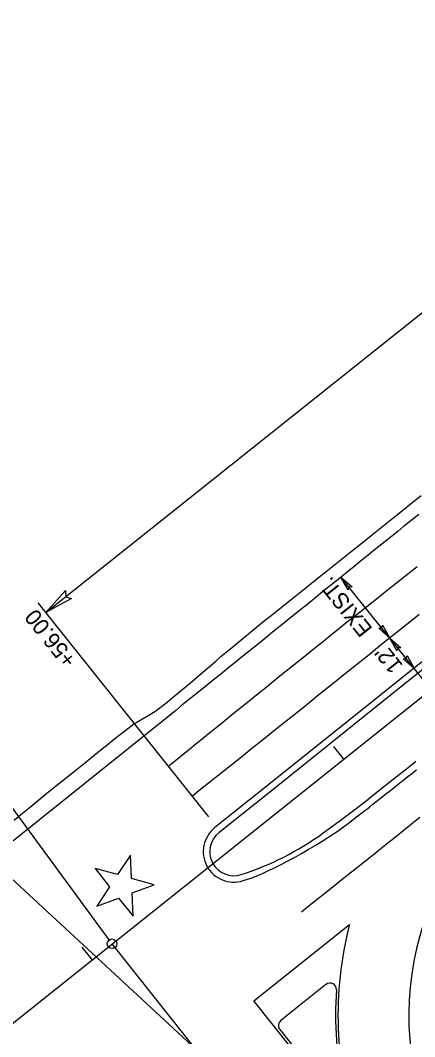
# Model space of a CAD drawing. Extents: x 472216 to 481979, y 489069 to 507339.
# Drawn here: x 473629 to 473751.6, y 506201.2 to 506517.1 of the extents above; entities that cross this region are included whole.
import ezdxf

# ---------------------------------------------------------------- set-up
doc = ezdxf.new("R2010")
doc.units = 0
for name, color, linetype in [('Old_Level_12', 7, 'Continuous'), ('Prop Drainage Structure Outlet Berm Ditch 850 10 CELL', 7, 'Continuous'), ('Prop Drainage Structure Pipe CSP 15in', 7, 'Continuous'), ('Prop Drainage Structure Pipe RCP 15in Class III Label', 7, 'Continuous'), ('Prop Drainage Structure Pipe RCP 18in Class III Label', 7, 'Continuous'), ('Prop Drainage Structure Pipe RCP 24in Class III Label', 7, 'Continuous'), ('Prop Erosion Embankment Toe Protection CELL', 7, 'Continuous'), ('Prop Erosion Embankment Toe Protection Label', 7, 'Continuous'), ('Prop Horizontal Alignment Station Label', 7, 'Continuous'), ('Sheet Block Revision CELL', 7, 'Continuous'), ('Sheet North Arrow Point CELL', 7, 'Continuous'), ('Sheet PE Seal Cell', 7, 'Continuous')]:
    doc.layers.add(name, color=color, linetype=linetype)

msp = doc.modelspace()

# ---------------------------------------------------------------- linework, layer by layer
at = {"layer": 'Old_Level_12'}
for p, q in [((473656.69, 506231.26), (473522.92, 506413.56)), ((473683.68, 506197.16), (473500.48, 506366.9))]:
    msp.add_line(p, q, dxfattribs=at)
msp.add_circle((473657.57, 506230.05), 1.5, dxfattribs=at)
msp.add_circle((473657.57, 506230.05), 1.5, dxfattribs=at)
msp.add_circle((473657.57, 506230.05), 1.5, dxfattribs=at)
msp.add_circle((473657.57, 506230.05), 1.5, dxfattribs=at)
at = {"layer": 'Prop Drainage Structure Outlet Berm Ditch 850 10 CELL'}
for points in [[(473730.91, 506340.03), (473728.7, 506344.03), (473732.15, 506341), (473731.17, 506340.94)], [(473644.98, 506337.41), (473636.98, 506333.01), (473643.05, 506339.9), (473643.15, 506337.94)], [(473741.65, 506329.09), (473743.86, 506325.09), (473740.41, 506328.12), (473741.39, 506328.17)], [(473746.07, 506321.09), (473743.86, 506325.09), (473747.31, 506322.06), (473746.33, 506322)], [(473749.23, 506319.62), (473751.44, 506315.62), (473747.98, 506318.65), (473748.97, 506318.71)]]:
    msp.add_lwpolyline(points, close=True, dxfattribs=at)
at = {"layer": 'Prop Drainage Structure Pipe RCP 15in Class III Label'}
for p, q in [((473701.63, 506212.36), (473731.35, 506236.06)), ((473733.69, 506171.98), (473701.63, 506212.36))]:
    msp.add_line(p, q, dxfattribs=at)
msp.add_arc((473839.76, 506207.93), 112, 165.4515, 198.722, dxfattribs=at)
at = {"layer": 'Prop Drainage Structure Pipe RCP 18in Class III Label'}
msp.add_lwpolyline([(473659.58, 506244.29), (473664.09, 506238.61), (473663.78, 506245.86), (473670.59, 506248.4), (473663.58, 506250.35), (473663.27, 506257.61), (473659.26, 506251.55), (473652.26, 506253.5), (473656.78, 506247.81), (473652.77, 506241.75), (473659.58, 506244.29)], dxfattribs=at)
msp.add_lwpolyline([(473659.58, 506244.29), (473664.09, 506238.61), (473663.78, 506245.86), (473670.59, 506248.4), (473663.58, 506250.35), (473663.27, 506257.61), (473659.26, 506251.55), (473652.26, 506253.5), (473656.78, 506247.81), (473652.77, 506241.75), (473659.58, 506244.29)], dxfattribs=at)
at = {"layer": 'Prop Drainage Structure Pipe RCP 24in Class III Label'}
for p, q in [((473600.83, 506241.3), (473676.26, 506301.73)), ((473698.32, 506249.68), (473701.36, 506250.67))]:
    msp.add_line(p, q, dxfattribs=at)
for points in [[(474009.26, 506521.83), (473992, 506508.53), (473990.3, 506507.18), (473981.12, 506499.85), (473971.51, 506492.2), (473962.33, 506484.88), (473952.75, 506477.25), (473943.6, 506469.95), (473934.44, 506462.65), (473924.91, 506455.03), (473915.79, 506447.72), (473906.27, 506440.08), (473897.18, 506432.8), (473888.11, 506425.54), (473877.44, 506416.99), (473868.47, 506409.76), (473855.37, 506399.15), (473839.04, 506386.02), (473812.65, 506364.8), (473778.08, 506337.11), (473740.52, 506306.99), (473705.74, 506279.1), (473689.48, 506266.16)], [(473752.86, 506363.48), (473750.91, 506361.92), (473748.95, 506360.36), (473748.26, 506359.81), (473746.32, 506358.24), (473744.37, 506356.67), (473742.43, 506355.1), (473740.48, 506353.53), (473738.54, 506351.96), (473736.6, 506350.4), (473734.65, 506348.83), (473732.71, 506347.26), (473730.76, 506345.69), (473728.82, 506344.12), (473726.87, 506342.55), (473724.93, 506340.99), (473722.98, 506339.42), (473721.04, 506337.85), (473719.09, 506336.28), (473717.15, 506334.71), (473715.2, 506333.14), (473713.26, 506331.58), (473711.31, 506330.01), (473709.37, 506328.44), (473707.42, 506326.87), (473705.48, 506325.3), (473703.54, 506323.73), (473701.59, 506322.17), (473699.65, 506320.6), (473697.7, 506319.03), (473695.76, 506317.46), (473693.81, 506315.89), (473691.87, 506314.32), (473689.92, 506312.76), (473687.98, 506311.19), (473686.03, 506309.62), (473684.09, 506308.05), (473682.14, 506306.48), (473680.2, 506304.91), (473679.17, 506304.08), (473677.23, 506302.51), (473675.29, 506300.94), (473674.72, 506300.49), (473674.64, 506300.43)], [(473701.31, 506250.65), (473703.61, 506251.62), (473704.11, 506251.83), (473706.37, 506252.89), (473707.86, 506253.59), (473710.08, 506254.72), (473712, 506255.69), (473714.2, 506256.88), (473716.4, 506258.08), (473718.55, 506259.35), (473720.7, 506260.61), (473722.81, 506261.96), (473724.63, 506263.12), (473726.72, 506264.48), (473726.96, 506264.63), (473727.8, 506265.21), (473729.06, 506266.1), (473731.07, 506267.58), (473731.6, 506267.96), (473733.57, 506269.5), (473735.54, 506271.03), (473737.51, 506272.57), (473738.63, 506273.44), (473740.6, 506274.99), (473742.56, 506276.54), (473744.04, 506277.71), (473746, 506279.26), (473747.96, 506280.81), (473749.91, 506282.37), (473750.16, 506282.57), (473752.12, 506284.12)]]:
    msp.add_lwpolyline(points, dxfattribs=at)
for centre, radius, start, end in [((473839.76, 506207.93), 90, 129.7563, 213.9898), ((473695.4, 506258.72), 9.5, 128.5099, 287.9281)]:
    msp.add_arc(centre, radius, start, end, dxfattribs=at)
at = {"layer": 'Prop Erosion Embankment Toe Protection CELL'}
for points in [[(474010.48, 506520.25), (473993.23, 506506.96), (473991.54, 506505.62), (473982.36, 506498.29), (473972.76, 506490.64), (473963.58, 506483.31), (473954, 506475.69), (473944.84, 506468.38), (473935.69, 506461.09), (473926.16, 506453.46), (473917.05, 506446.16), (473907.52, 506438.52), (473898.43, 506431.24), (473889.36, 506423.98), (473878.69, 506415.43), (473869.73, 506408.21), (473856.63, 506397.6), (473840.3, 506384.46), (473813.9, 506363.24), (473779.33, 506335.55), (473741.77, 506305.43), (473706.99, 506277.53), (473690.73, 506264.59)], [(473627.16, 506268.53), (473629.73, 506270.63), (473632.26, 506272.71), (473634.79, 506274.78), (473637.33, 506276.85), (473639.86, 506278.91), (473642.37, 506280.94), (473644.8, 506282.91), (473649.46, 506286.66), (473653.61, 506289.98), (473655.42, 506291.42), (473658.45, 506293.83), (473662.84, 506297.32), (473664.32, 506298.37), (473668.99, 506301.07), (473671.17, 506302.47), (473674.16, 506304.74), (473678, 506307.91), (473681.88, 506311.21), (473685.74, 506314.51), (473689.77, 506317.94), (473691.51, 506319.41), (473694.47, 506321.87), (473696.93, 506323.93), (473700.56, 506326.95), (473704.31, 506329.97), (473706.58, 506331.8), (473709.08, 506333.79), (473711.81, 506335.97), (473714.76, 506338.32), (473717.9, 506340.82), (473721.19, 506343.45), (473724.63, 506346.2), (473728.22, 506349.08), (473731.82, 506351.96), (473735.27, 506354.72), (473738.57, 506357.36), (473741.73, 506359.87), (473744.79, 506362.31), (473747.79, 506364.72), (473750.73, 506367.09), (473753.63, 506369.43)], [(473723.15, 506264.5), (473725.76, 506266.39), (473728.46, 506268.36), (473733.01, 506271.76), (473736.49, 506274.45), (473740.51, 506277.65), (473744.93, 506281.19), (473749.58, 506284.89), (473752.01, 506286.81)]]:
    msp.add_lwpolyline(points, dxfattribs=at)
for centre, radius, start, end in [((473695.4, 506258.72), 7.5, 128.5099, 287.772), ((473670.21, 506337.28), 90, 287.772, 306.0274)]:
    msp.add_arc(centre, radius, start, end, dxfattribs=at)
at = {"layer": 'Prop Erosion Embankment Toe Protection Label'}
for points in [[(473752.37, 506347.24), (473750.41, 506345.69), (473748.45, 506344.13), (473746.49, 506342.58), (473744.53, 506341.03), (473742.58, 506339.48), (473740.62, 506337.93), (473738.66, 506336.37), (473736.7, 506334.82), (473734.75, 506333.27), (473732.79, 506331.72), (473731.16, 506330.42), (473729.21, 506328.86), (473727.26, 506327.29), (473725.31, 506325.73), (473723.37, 506324.16), (473721.42, 506322.6), (473719.47, 506321.03), (473717.53, 506319.46), (473715.58, 506317.9), (473713.63, 506316.33), (473711.69, 506314.77), (473709.74, 506313.2), (473707.79, 506311.64), (473705.85, 506310.07), (473703.9, 506308.5), (473701.95, 506306.94), (473701.05, 506306.21), (473699.11, 506304.64), (473697.17, 506303.07), (473695.23, 506301.5), (473693.28, 506299.93), (473691.34, 506298.35), (473689.4, 506296.78), (473687.46, 506295.21), (473685.52, 506293.64), (473683.57, 506292.07), (473681.63, 506290.49), (473679.69, 506288.92), (473677.75, 506287.35), (473675.81, 506285.78), (473675.3, 506285.37)], [(473753.04, 506332.41), (473751.09, 506330.85), (473749.14, 506329.28), (473747.19, 506327.72), (473745.24, 506326.16), (473743.29, 506324.59), (473741.34, 506323.03), (473739.39, 506321.47), (473737.45, 506319.91), (473735.5, 506318.34), (473733.55, 506316.78), (473733.01, 506316.35), (473731.06, 506314.79), (473729.11, 506313.22), (473727.16, 506311.66), (473725.21, 506310.1), (473723.26, 506308.53), (473721.32, 506306.97), (473719.37, 506305.41), (473717.42, 506303.84), (473715.47, 506302.28), (473713.52, 506300.72), (473711.57, 506299.15), (473709.62, 506297.59), (473707.67, 506296.03), (473705.72, 506294.46), (473703.78, 506292.9), (473701.83, 506291.34), (473699.88, 506289.77), (473698.25, 506288.47), (473696.3, 506286.92), (473694.34, 506285.36), (473692.39, 506283.8), (473690.43, 506282.25), (473688.48, 506280.69), (473686.52, 506279.14), (473684.57, 506277.58), (473682.61, 506276.03), (473682.5, 506275.93)], [(473716.38, 506239.94), (473718.33, 506241.5), (473720.28, 506243.06), (473722.23, 506244.62), (473724.18, 506246.18), (473726.13, 506247.74), (473728.08, 506249.3), (473730.03, 506250.86), (473731.98, 506252.42), (473733.93, 506253.98), (473735.88, 506255.54), (473737.84, 506257.1), (473739.79, 506258.66), (473741.74, 506260.22), (473743.69, 506261.78), (473745.64, 506263.34), (473747.37, 506264.73), (473749.32, 506266.29), (473751.26, 506267.85), (473753.21, 506269.42)]]:
    msp.add_lwpolyline(points, dxfattribs=at)
at = {"layer": 'Prop Horizontal Alignment Station Label'}
msp.add_line((473724.04, 506217.44), (473709.99, 506206.24), dxfattribs=at)
msp.add_lwpolyline([(473709.67, 506203.43), (473712.03, 506200.46), (473725.92, 506182.96)], dxfattribs=at)
for centre, radius, start, end in [((473725.29, 506215.88), 2, 356.0286, 128.5744), ((473839.76, 506207.93), 112.75, 176.0286, 191.9302), ((473839.76, 506207.93), 112.75, 176.0286, 191.9302), ((473711.24, 506204.67), 2, 128.5744, 218.4488)]:
    msp.add_arc(centre, radius, start, end, dxfattribs=at)
at = {"layer": 'Sheet Block Revision CELL'}
for p, q in [((473636.98, 506333.01), (474023.96, 506641.65)), ((473751.43, 506315.63), (473728.7, 506344.03)), ((473763.88, 506300.07), (473728.7, 506344.03)), ((473687.61, 506269.53), (473634.57, 506336.02))]:
    msp.add_line(p, q, dxfattribs=at)
at = {"layer": 'Sheet North Arrow Point CELL'}
for p, q in [((473181.18, 505850.11), (474073.29, 506561.61)), ((474109.5, 505660.85), (473657.57, 506230.05))]:
    msp.add_line(p, q, dxfattribs=at)
at = {"layer": 'Sheet PE Seal Cell'}
for p, q in [((473729.57, 506287.48), (473726.45, 506291.39)), ((473651.39, 506225.13), (473648.27, 506229.04))]:
    msp.add_line(p, q, dxfattribs=at)

# ---------------------------------------------------------------- texts
at = {"layer": 'Prop Drainage Structure Pipe CSP 15in'}
for s, rotation, p in [('EXIST.', 128.6712, (473738.72, 506328)), ('+56.00', 128.4488, (473646.78, 506318.37)), ("12'", 128.6712, (473748.16, 506316.58))]:
    msp.add_text(s, height=5, rotation=rotation, dxfattribs=at).set_placement(p)

doc.saveas('drawing.dxf')
